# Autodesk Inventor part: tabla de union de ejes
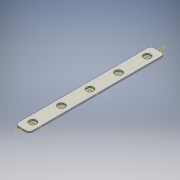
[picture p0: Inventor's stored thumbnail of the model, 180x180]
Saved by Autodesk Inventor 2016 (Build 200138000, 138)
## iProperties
Created: 2016-06
Part Number: tabla de union de ejes
Material: Genérico
Document SubType Name: Modeling
Designer: adm
Density: 1 g/cm^3
Appearance: Valor por defecto
Author: adm
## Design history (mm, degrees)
sketch "Boceto1"
  geometry: L1 (-20, -190)-(20, -190); L2 (20, -190)-(20, 190); L3 (20, 190)-(-20, 190); L4 (-20, 190)-(-20, -190); L5 (-20, -190)-(20, 190); L6 (20, -190)-(-20, 190); 1 further point
  constraints: 12 end point, 2 midpoint, 2 parallel, 1 horizontal, 1 perpendicular
  dimensions: "d0" = 40 distance of L2.end L3.end; "d1" = 380 distance of L1.end L2.end
extrude "Extrusión1" new body sketch "Boceto1" distance "d2" = 4; taper "d3" = 0 deg
fillet "Empalme1" dims "d4" = 10
fillet "Empalme2" dims "d5" = 10
sketch "Boceto2"
  geometry: L1 (10, 190)-(-10, 190) reference; L2 (-10, -190)-(10, -190) reference; C1 r 10 at (0, 160); C2 r 10 at (0, 80); C3 r 10 at (0, 0); C4 r 10 at (0, -80); C5 r 10 at (0, -160); 6 further points
  constraints: 5 centre point, 5 coincident
  dimensions: "d6" = 30 distance from line of point (0, 160) L1; "d11" = 30 distance from line of L2 point (0, -160); "d12" = 20 diameter of C1; "d13" = 20 diameter of C2; "d14" = 20 diameter of C3; "d15" = 20 diameter of C4; "d16" = 20 diameter of C5; "d19" = 80 distance of point (0, 80) point (0, 160); "d20" = 80 distance of point (0, 0) point (0, 80); "d21" = 80 distance of point (0, -80) point (0, 0)
extrude "Extrusión2" cut sketch "Boceto2" distance "d17" = 4; taper "d18" = 0 deg
node "Plano de trabajo1"
node "Sólido1"
